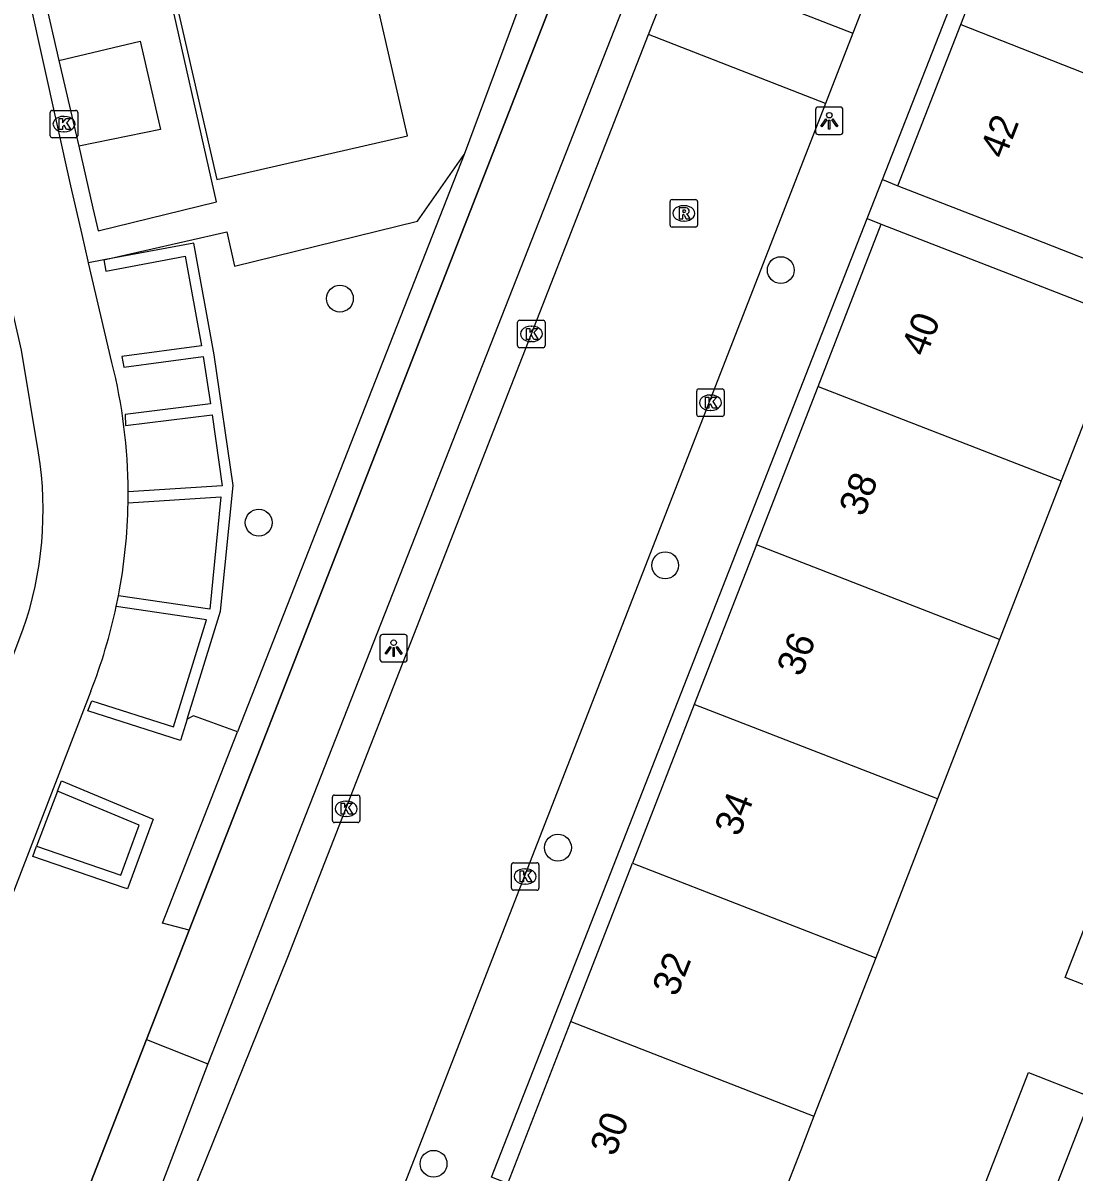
# Model space of a CAD drawing. Extents: x 161253 to 161848, y 384872 to 385383.
# Drawn here: x 161611.23 to 161649.49, y 385146.52 to 385188.35 of the extents above; entities that cross this region are included whole.
import ezdxf

# ---------------------------------------------------------------- set-up
doc = ezdxf.new("R2010")
doc.units = 0
for name, color, linetype in [('IMGEO_Boom', 7, 'Continuous'), ('IMGEO_Groenvoorziening', 7, 'Continuous'), ('IMGEO_Haag', 7, 'Continuous'), ('IMGEO_Hek', 7, 'Continuous'), ('IMGEO_Kolk', 7, 'Continuous'), ('IMGEO_Lichtpunt', 7, 'Continuous'), ('IMGEO_Pand', 7, 'Continuous'), ('IMGEO_Pand_nummerreeks', 7, 'Continuous'), ('IMGEO_Rijbaan_lokaal_open', 7, 'Continuous'), ('IMGEO_Rioolput', 7, 'Continuous'), ('IMGEO_Voetpad_gesloten', 7, 'Continuous'), ('IMGEO_Voetpad_open', 7, 'Continuous')]:
    doc.layers.add(name, color=color, linetype=linetype)

msp = doc.modelspace()

# ---------------------------------------------------------------- linework, layer by layer
at = {"layer": 'IMGEO_Boom'}
for centre in [(161638.818, 385179.355), (161622.765, 385178.318), (161619.811, 385170.162), (161634.608, 385168.608), (161630.703, 385158.33), (161626.175, 385146.821)]:
    msp.add_circle(centre, 0.489, dxfattribs=at)
at = {"layer": 'IMGEO_Groenvoorziening'}
for points in [[(161613.255, 385183.866), (161613.774, 385181.612), (161613.964, 385180.783), (161618.271, 385181.836), (161616.367, 385190.299)], [(161612.008, 385189.279), (161612.537, 385186.981)], [(161612.537, 385186.981), (161615.497, 385187.685), (161616.231, 385184.47), (161613.255, 385183.866)], [(161612.537, 385186.981), (161613.255, 385183.866)], [(161614.17, 385179.735), (161618.648, 385180.752), (161618.925, 385179.496), (161625.596, 385181.133), (161627.284, 385183.564)], [(161614.17, 385179.735), (161613.615, 385179.618)], [(161619.042, 385162.548), (161617.43, 385163.13), (161617.206, 385163.007)], [(161612.482, 385160.39), (161611.722, 385158.385)], [(161615.729, 385151.345), (161617.282, 385155.322)], [(161612.34, 385142.048), (161612.128, 385142.128), (161612.168, 385142.23), (161615.729, 385151.345)], [(161615.729, 385151.345), (161617.957, 385150.456)]]:
    msp.add_lwpolyline(points, dxfattribs=at)
at = {"layer": 'IMGEO_Haag'}
for points in [[(161617.282, 385155.322), (161619.974, 385162.211), (161628.431, 385183.861), (161637.478, 385207.021), (161643.668, 385222.865)], [(161636.496, 385208.343), (161627.284, 385183.564)], [(161627.284, 385183.564), (161619.042, 385162.548)], [(161617.206, 385163.007), (161618.418, 385166.934), (161618.878, 385171.515), (161618.188, 385176.271), (161617.447, 385180.331), (161614.17, 385179.735)], [(161614.17, 385179.735), (161614.248, 385179.314), (161617.126, 385179.863), (161617.721, 385176.605), (161614.821, 385176.216), (161614.894, 385175.822), (161617.793, 385176.211), (161618.056, 385174.482), (161614.952, 385174.095), (161614.965, 385173.694), (161618.116, 385174.086), (161618.475, 385171.507), (161615.056, 385171.281)], [(161615.053, 385170.879), (161618.434, 385171.103), (161618.024, 385167.014), (161614.703, 385167.503)], [(161617.206, 385163.007), (161616.965, 385162.226), (161613.587, 385163.306), (161613.729, 385163.681), (161616.702, 385162.73), (161617.905, 385166.627), (161614.624, 385167.11)], [(161617.282, 385155.322), (161616.31, 385155.581), (161619.042, 385162.548)], [(161612.482, 385160.39), (161612.624, 385160.764), (161615.967, 385159.369), (161615.027, 385156.826), (161614.908, 385156.866), (161611.58, 385158.011), (161611.722, 385158.385)], [(161611.722, 385158.385), (161614.787, 385157.331), (161615.459, 385159.148), (161612.482, 385160.39)]]:
    msp.add_lwpolyline(points, dxfattribs=at)
at = {"layer": 'IMGEO_Hek'}
for points in [[(161637.478, 385207.021), (161628.431, 385183.861)], [(161628.431, 385183.861), (161619.974, 385162.211)], [(161619.974, 385162.211), (161617.282, 385155.322)], [(161617.282, 385155.322), (161615.729, 385151.345)], [(161615.729, 385151.345), (161612.168, 385142.23)]]:
    msp.add_lwpolyline(points, dxfattribs=at)
at = {"layer": 'IMGEO_Kolk'}
for p, q in [((161612.22, 385184.246), (161612.22, 385185.098)), ((161612.295, 385185.172), (161613.147, 385185.172)), ((161613.221, 385185.098), (161613.221, 385184.246)), ((161612.708, 385184.952), (161612.733, 385184.952)), ((161612.731, 385184.392), (161612.706, 385184.392)), ((161613.147, 385184.172), (161612.295, 385184.172)), ((161629.312, 385177.532), (161630.164, 385177.532)), ((161629.237, 385176.606), (161629.237, 385177.458)), ((161629.725, 385177.312), (161629.75, 385177.312)), ((161630.238, 385177.458), (161630.238, 385176.606)), ((161629.748, 385176.752), (161629.723, 385176.752)), ((161630.164, 385176.532), (161629.312, 385176.532)), ((161635.83, 385175.028), (161636.682, 385175.028)), ((161635.755, 385174.102), (161635.755, 385174.954)), ((161636.243, 385174.808), (161636.268, 385174.808)), ((161636.756, 385174.954), (161636.756, 385174.102)), ((161636.266, 385174.248), (161636.241, 385174.248)), ((161636.682, 385174.028), (161635.83, 385174.028)), ((161622.492, 385159.319), (161622.492, 385160.171)), ((161622.567, 385160.245), (161623.419, 385160.245)), ((161622.98, 385160.025), (161623.005, 385160.025)), ((161623.493, 385160.171), (161623.493, 385159.319)), ((161623.419, 385159.245), (161622.567, 385159.245)), ((161623.003, 385159.465), (161622.978, 385159.465)), ((161629.012, 385156.855), (161629.012, 385157.707)), ((161629.087, 385157.781), (161629.939, 385157.781)), ((161629.5, 385157.561), (161629.525, 385157.561)), ((161630.013, 385157.707), (161630.013, 385156.855)), ((161629.939, 385156.781), (161629.087, 385156.781)), ((161629.523, 385157.001), (161629.498, 385157.001))]:
    msp.add_line(p, q, dxfattribs=at)
for points in [[(161612.22, 385184.246), (161612.22, 385185.098)], [(161612.295, 385185.172), (161613.147, 385185.172)], [(161613.221, 385185.098), (161613.221, 385184.246)], [(161612.541, 385184.872), (161612.664, 385184.872), (161612.664, 385184.721), (161612.794, 385184.872), (161612.958, 385184.872), (161612.812, 385184.721), (161612.965, 385184.472), (161612.813, 385184.472), (161612.728, 385184.636), (161612.664, 385184.569), (161612.664, 385184.472), (161612.541, 385184.472), (161612.541, 385184.872)], [(161613.147, 385184.172), (161612.295, 385184.172)], [(161629.312, 385177.532), (161630.164, 385177.532)], [(161629.237, 385176.606), (161629.237, 385177.458)], [(161629.558, 385177.232), (161629.681, 385177.232), (161629.681, 385177.081), (161629.811, 385177.232), (161629.975, 385177.232), (161629.829, 385177.081), (161629.982, 385176.832), (161629.83, 385176.832), (161629.745, 385176.996), (161629.681, 385176.929), (161629.681, 385176.832), (161629.558, 385176.832), (161629.558, 385177.232)], [(161630.238, 385177.458), (161630.238, 385176.606)], [(161630.164, 385176.532), (161629.312, 385176.532)], [(161635.83, 385175.028), (161636.682, 385175.028)], [(161635.755, 385174.102), (161635.755, 385174.954)], [(161636.076, 385174.728), (161636.199, 385174.728), (161636.199, 385174.577), (161636.329, 385174.728), (161636.493, 385174.728), (161636.347, 385174.577), (161636.5, 385174.328), (161636.348, 385174.328), (161636.263, 385174.492), (161636.199, 385174.425), (161636.199, 385174.328), (161636.076, 385174.328), (161636.076, 385174.728)], [(161636.756, 385174.954), (161636.756, 385174.102)], [(161636.682, 385174.028), (161635.83, 385174.028)], [(161622.492, 385159.319), (161622.492, 385160.171)], [(161622.567, 385160.245), (161623.419, 385160.245)], [(161623.493, 385160.171), (161623.493, 385159.319)], [(161622.813, 385159.945), (161622.936, 385159.945), (161622.936, 385159.794), (161623.066, 385159.945), (161623.23, 385159.945), (161623.084, 385159.794), (161623.237, 385159.545), (161623.085, 385159.545), (161623, 385159.709), (161622.936, 385159.642), (161622.936, 385159.545), (161622.813, 385159.545), (161622.813, 385159.945)], [(161623.419, 385159.245), (161622.567, 385159.245)], [(161629.012, 385156.855), (161629.012, 385157.707)], [(161629.087, 385157.781), (161629.939, 385157.781)], [(161629.333, 385157.481), (161629.456, 385157.481), (161629.456, 385157.33), (161629.586, 385157.481), (161629.75, 385157.481), (161629.604, 385157.33), (161629.757, 385157.081), (161629.605, 385157.081), (161629.52, 385157.245), (161629.456, 385157.178), (161629.456, 385157.081), (161629.333, 385157.081), (161629.333, 385157.481)], [(161630.013, 385157.707), (161630.013, 385156.855)], [(161629.939, 385156.781), (161629.087, 385156.781)]]:
    msp.add_lwpolyline(points, dxfattribs=at)
for centre, start, end in [((161612.297, 385185.096), 91.552, 178.448), ((161612.297, 385185.096), 91.552, 178.448), ((161613.145, 385185.096), 1.552, 88.448), ((161613.145, 385185.096), 1.552, 88.448), ((161612.297, 385184.248), 181.552, 268.448), ((161612.297, 385184.248), 181.552, 268.448), ((161613.145, 385184.248), 271.552, 358.448), ((161613.145, 385184.248), 271.552, 358.448), ((161629.314, 385177.456), 91.552, 178.448), ((161629.314, 385177.456), 91.552, 178.448), ((161630.162, 385177.456), 1.552, 88.448), ((161630.162, 385177.456), 1.552, 88.448), ((161629.314, 385176.608), 181.552, 268.448), ((161629.314, 385176.608), 181.552, 268.448), ((161630.162, 385176.608), 271.552, 358.448), ((161630.162, 385176.608), 271.552, 358.448), ((161635.832, 385174.952), 91.552, 178.448), ((161635.832, 385174.952), 91.552, 178.448), ((161636.68, 385174.952), 1.552, 88.448), ((161636.68, 385174.952), 1.552, 88.448), ((161635.832, 385174.104), 181.552, 268.448), ((161635.832, 385174.104), 181.552, 268.448), ((161636.68, 385174.104), 271.552, 358.448), ((161636.68, 385174.104), 271.552, 358.448), ((161622.569, 385160.169), 91.552, 178.448), ((161622.569, 385160.169), 91.552, 178.448), ((161623.417, 385160.169), 1.552, 88.448), ((161623.417, 385160.169), 1.552, 88.448), ((161622.569, 385159.321), 181.552, 268.448), ((161622.569, 385159.321), 181.552, 268.448), ((161623.417, 385159.321), 271.552, 358.448), ((161623.417, 385159.321), 271.552, 358.448), ((161629.089, 385157.705), 91.552, 178.448), ((161629.089, 385157.705), 91.552, 178.448), ((161629.937, 385157.705), 1.552, 88.448), ((161629.937, 385157.705), 1.552, 88.448), ((161629.089, 385156.857), 181.552, 268.448), ((161629.089, 385156.857), 181.552, 268.448), ((161629.937, 385156.857), 271.552, 358.448), ((161629.937, 385156.857), 271.552, 358.448)]:
    msp.add_arc(centre, 0.0765, start, end, dxfattribs=at)
for centre, major_axis, ratio, start_param, end_param in [((161612.707, 385184.672), (-0.387, 0.002), 0.722429, 4.712389, 7.853982), ((161612.732, 385184.672), (-0.39, 0.002), 0.717154, 1.570796, 4.712389), ((161629.724, 385177.032), (-0.387, 0.002), 0.722429, 4.712389, 7.853982), ((161629.749, 385177.032), (-0.39, 0.002), 0.717154, 1.570796, 4.712389), ((161636.242, 385174.528), (-0.387, 0.002), 0.722429, 4.712389, 7.853982), ((161636.267, 385174.528), (-0.39, 0.002), 0.717154, 1.570796, 4.712389), ((161622.979, 385159.745), (-0.387, 0.002), 0.722429, 4.712389, 7.853982), ((161623.004, 385159.745), (-0.39, 0.002), 0.717154, 1.570796, 4.712389), ((161629.499, 385157.281), (-0.387, 0.002), 0.722429, 4.712389, 7.853982), ((161629.524, 385157.281), (-0.39, 0.002), 0.717154, 1.570796, 4.712389)]:
    msp.add_ellipse(centre, major_axis=major_axis, ratio=ratio, start_param=start_param, end_param=end_param, dxfattribs=at)
at = {"layer": 'IMGEO_Lichtpunt'}
for p, q in [((161640.084, 385185.195), (161640.084, 385184.388)), ((161640.084, 385185.195), (161640.084, 385184.388)), ((161640.986, 385185.29), (161640.178, 385185.29)), ((161640.986, 385185.29), (161640.178, 385185.29)), ((161641.08, 385184.388), (161641.08, 385185.195)), ((161641.08, 385184.388), (161641.08, 385185.195)), ((161640.178, 385184.294), (161640.986, 385184.294)), ((161640.178, 385184.294), (161640.986, 385184.294)), ((161624.223, 385165.995), (161624.223, 385165.188)), ((161624.223, 385165.995), (161624.223, 385165.188)), ((161625.125, 385166.09), (161624.317, 385166.09)), ((161625.125, 385166.09), (161624.317, 385166.09)), ((161625.219, 385165.188), (161625.219, 385165.995)), ((161625.219, 385165.188), (161625.219, 385165.995)), ((161624.317, 385165.094), (161625.125, 385165.094)), ((161624.317, 385165.094), (161625.125, 385165.094))]:
    msp.add_line(p, q, dxfattribs=at)
for points in [[(161640.458, 385184.859), (161640.497, 385184.831), (161640.309, 385184.569), (161640.271, 385184.596), (161640.458, 385184.859)], [(161640.56, 385184.811), (161640.607, 385184.811), (161640.607, 385184.489), (161640.56, 385184.489), (161640.56, 385184.811)], [(161640.67, 385184.831), (161640.708, 385184.858), (161640.895, 385184.596), (161640.856, 385184.568), (161640.67, 385184.831)], [(161624.597, 385165.659), (161624.636, 385165.631), (161624.448, 385165.369), (161624.41, 385165.396), (161624.597, 385165.659)], [(161624.699, 385165.611), (161624.746, 385165.611), (161624.746, 385165.289), (161624.699, 385165.289), (161624.699, 385165.611)], [(161624.809, 385165.631), (161624.847, 385165.658), (161625.034, 385165.396), (161624.995, 385165.368), (161624.809, 385165.631)]]:
    msp.add_lwpolyline(points, dxfattribs=at)
for centre in [(161640.583, 385184.993), (161624.722, 385165.793)]:
    msp.add_circle(centre, 0.0994, dxfattribs=at)
for centre, start, end in [((161640.178, 385185.195), 90, 180), ((161640.178, 385185.195), 90, 180), ((161640.986, 385185.195), 0, 90), ((161640.986, 385185.195), 0, 90), ((161640.178, 385184.388), 180, 270), ((161640.178, 385184.388), 180, 270), ((161640.986, 385184.388), 270, 0), ((161640.986, 385184.388), 270, 360), ((161624.317, 385165.995), 90, 180), ((161624.317, 385165.995), 90, 180), ((161625.125, 385165.995), 0, 90), ((161625.125, 385165.995), 0, 90), ((161624.317, 385165.188), 180, 270), ((161624.317, 385165.188), 180, 270), ((161625.125, 385165.188), 270, 0), ((161625.125, 385165.188), 270, 360)]:
    msp.add_arc(centre, 0.0946, start, end, dxfattribs=at)
at = {"layer": 'IMGEO_Pand'}
for points in [[(161618.29, 385182.65), (161625.229, 385184.243), (161622.605, 385195.663), (161615.667, 385194.069), (161618.29, 385182.65)], [(161645.371, 385188.297), (161647.622, 385194.063)], [(161643.081, 385182.429), (161645.371, 385188.297)], [(161645.371, 385188.297), (161654.193, 385184.823)], [(161643.081, 385182.429), (161647.739, 385180.61), (161651.916, 385178.978)], [(161640.175, 385175.123), (161642.475, 385181.032)], [(161642.475, 385181.032), (161647.135, 385179.218), (161651.327, 385177.586)], [(161651.327, 385177.586), (161649.028, 385171.681)], [(161637.929, 385169.353), (161640.175, 385175.123)], [(161640.175, 385175.123), (161649.028, 385171.681)], [(161649.028, 385171.681), (161646.782, 385165.911)], [(161637.929, 385169.353), (161635.668, 385163.546)], [(161646.782, 385165.911), (161637.929, 385169.353)], [(161646.782, 385165.911), (161644.522, 385160.104)], [(161635.668, 385163.546), (161633.419, 385157.768)], [(161644.522, 385160.104), (161635.668, 385163.546)], [(161644.522, 385160.104), (161642.272, 385154.325)], [(161631.173, 385151.999), (161633.419, 385157.768)], [(161633.419, 385157.768), (161642.272, 385154.325)], [(161651.114, 385152.845), (161649.176, 385153.599), (161650.764, 385157.677)], [(161642.272, 385154.325), (161640.026, 385148.555)], [(161628.877, 385146.101), (161631.173, 385151.999)], [(161631.173, 385151.999), (161640.026, 385148.555)], [(161646.268, 385146.127), (161647.832, 385150.145), (161649.815, 385149.373)], [(161648.552, 385145.238), (161650.116, 385149.256), (161649.815, 385149.373)], [(161640.026, 385148.555), (161639.543, 385147.315), (161637.729, 385142.655)]]:
    msp.add_lwpolyline(points, dxfattribs=at)
at = {"layer": 'IMGEO_Rijbaan_lokaal_open'}
for points in [[(161654.892, 385250.594), (161654.91, 385250), (161655.402, 385234.118), (161655.423, 385232.416), (161655.214, 385228.331), (161654.641, 385224.281), (161653.708, 385220.298), (161652.424, 385216.415), (161648.956, 385207.28), (161641.438, 385187.982)], [(161634.002, 385187.929), (161635.004, 385190.489)], [(161635.004, 385190.489), (161641.438, 385187.982)], [(161616.012, 385142.32), (161620.865, 385154.341), (161634.002, 385187.929)], [(161640.44, 385185.42), (161634.002, 385187.929)], [(161641.438, 385187.982), (161640.44, 385185.42)], [(161640.44, 385185.42), (161622.644, 385139.739)]]:
    msp.add_lwpolyline(points, dxfattribs=at)
at = {"layer": 'IMGEO_Rioolput'}
for p, q in [((161634.785, 385180.996), (161634.785, 385181.848)), ((161634.86, 385181.922), (161635.712, 385181.922)), ((161635.786, 385181.848), (161635.786, 385180.996)), ((161635.273, 385181.702), (161635.298, 385181.702)), ((161635.712, 385180.922), (161634.86, 385180.922)), ((161635.296, 385181.142), (161635.271, 385181.142))]:
    msp.add_line(p, q, dxfattribs=at)
for points in [[(161634.785, 385180.996), (161634.785, 385181.848)], [(161634.86, 385181.922), (161635.712, 385181.922)], [(161635.786, 385181.848), (161635.786, 385180.996)], [(161635.374, 385181.62), (161635.122, 385181.622), (161635.122, 385181.222)], [(161635.122, 385181.222), (161635.246, 385181.222), (161635.246, 385181.384), (161635.257, 385181.384)], [(161635.3, 385181.541), (161635.246, 385181.541), (161635.246, 385181.46)], [(161635.246, 385181.46), (161635.298, 385181.46)], [(161635.304, 385181.355), (161635.375, 385181.222), (161635.515, 385181.222), (161635.45, 385181.348)], [(161635.712, 385180.922), (161634.86, 385180.922)]]:
    msp.add_lwpolyline(points, dxfattribs=at)
for centre, radius, start, end in [((161634.862, 385181.846), 0.0765, 91.552, 178.448), ((161634.862, 385181.846), 0.0765, 91.552, 178.448), ((161635.71, 385181.846), 0.0765, 1.552, 88.448), ((161635.71, 385181.846), 0.0765, 1.552, 88.448), ((161635.256, 385181.331), 0.0533, 26.0293, 88.6989), ((161635.282, 385181.649), 0.19, 274.7715, 282.9687), ((161635.306, 385181.445), 0.0964, 77.0061, 93.1865), ((161635.32, 385181.502), 0.0378, 276.6634, 79.6772), ((161635.373, 385181.51), 0.109, 350.3612, 89.416), ((161635.371, 385181.51), 0.112, 277.5842, 350.9817), ((161635.355, 385181.295), 0.108, 29.5134, 73.7905), ((161634.862, 385180.998), 0.0765, 181.552, 268.448), ((161634.862, 385180.998), 0.0765, 181.552, 268.448), ((161635.71, 385180.998), 0.0765, 271.552, 358.448), ((161635.71, 385180.998), 0.0765, 271.552, 358.448)]:
    msp.add_arc(centre, radius, start, end, dxfattribs=at)
for centre, major_axis, ratio, start_param, end_param in [((161635.272, 385181.422), (-0.387, 0.002), 0.722429, 4.712389, 7.853982), ((161635.297, 385181.422), (-0.39, 0.002), 0.717154, 1.570796, 4.712389)]:
    msp.add_ellipse(centre, major_axis=major_axis, ratio=ratio, start_param=start_param, end_param=end_param, dxfattribs=at)
at = {"layer": 'IMGEO_Voetpad_gesloten'}
for points in [[(161613.615, 385179.618), (161613.6, 385179.683), (161613.378, 385180.649), (161612.972, 385182.42), (161611.48, 385189.162)], [(161611.796, 385172.704), (161611.168, 385176.441), (161610.278, 385180.329)], [(161614.465, 385175.99), (161613.615, 385179.618)], [(161615.053, 385170.879), (161615.056, 385171.281)], [(161614.624, 385167.11), (161614.703, 385167.503)], [(161596.957, 385154.132), (161605.449, 385155.918), (161607.192, 385156.171), (161610.513, 385164.397), (161611.227, 385166.259)], [(161613.699, 385164.033), (161605.12, 385141.803)]]:
    msp.add_lwpolyline(points, dxfattribs=at)
for centre, radius, start, end in [((161595.382, 385171.203), 19.675, 0.2261, 14.0808), ((161598.651, 385170.617), 13.309, 340.8872, 9.0222), ((161595.409, 385171.209), 19.647, 349.1259, 359.0364), ((161595.233, 385171.262), 19.831, 338.6216, 347.915)]:
    msp.add_arc(centre, radius, start, end, dxfattribs=at)
at = {"layer": 'IMGEO_Voetpad_open'}
for points in [[(161642.519, 385182.649), (161655.412, 385215.533), (161656.675, 385219.233), (161657.602, 385223.032), (161658.187, 385226.898), (161658.366, 385229.85)], [(161645.653, 385220.933), (161617.957, 385150.456)], [(161641.964, 385181.232), (161642.519, 385182.649)], [(161642.519, 385182.649), (161643.081, 385182.429)], [(161628.877, 385146.101), (161628.283, 385146.338), (161641.964, 385181.232)], [(161641.964, 385181.232), (161642.475, 385181.032)], [(161617.957, 385150.456), (161614.501, 385141.406), (161614.443, 385141.247), (161612.34, 385142.048)]]:
    msp.add_lwpolyline(points, dxfattribs=at)

# ---------------------------------------------------------------- texts
at = {"layer": 'IMGEO_Pand_nummerreeks'}
for s, rotation, p in [('42', 68.679, (161646.966, 385183.363)), ('40', 68.7299, (161644.1, 385176.164)), ('38', 68.7299, (161641.834, 385170.342)), ('36', 68.7299, (161639.567, 385164.517)), ('34', 68.7299, (161637.3, 385158.696)), ('32', 68.7299, (161635.033, 385152.871)), ('30', 68.7299, (161632.769, 385147.055))]:
    msp.add_text(s, height=1, rotation=rotation, dxfattribs=at).set_placement(p)

doc.saveas('drawing.dxf')
